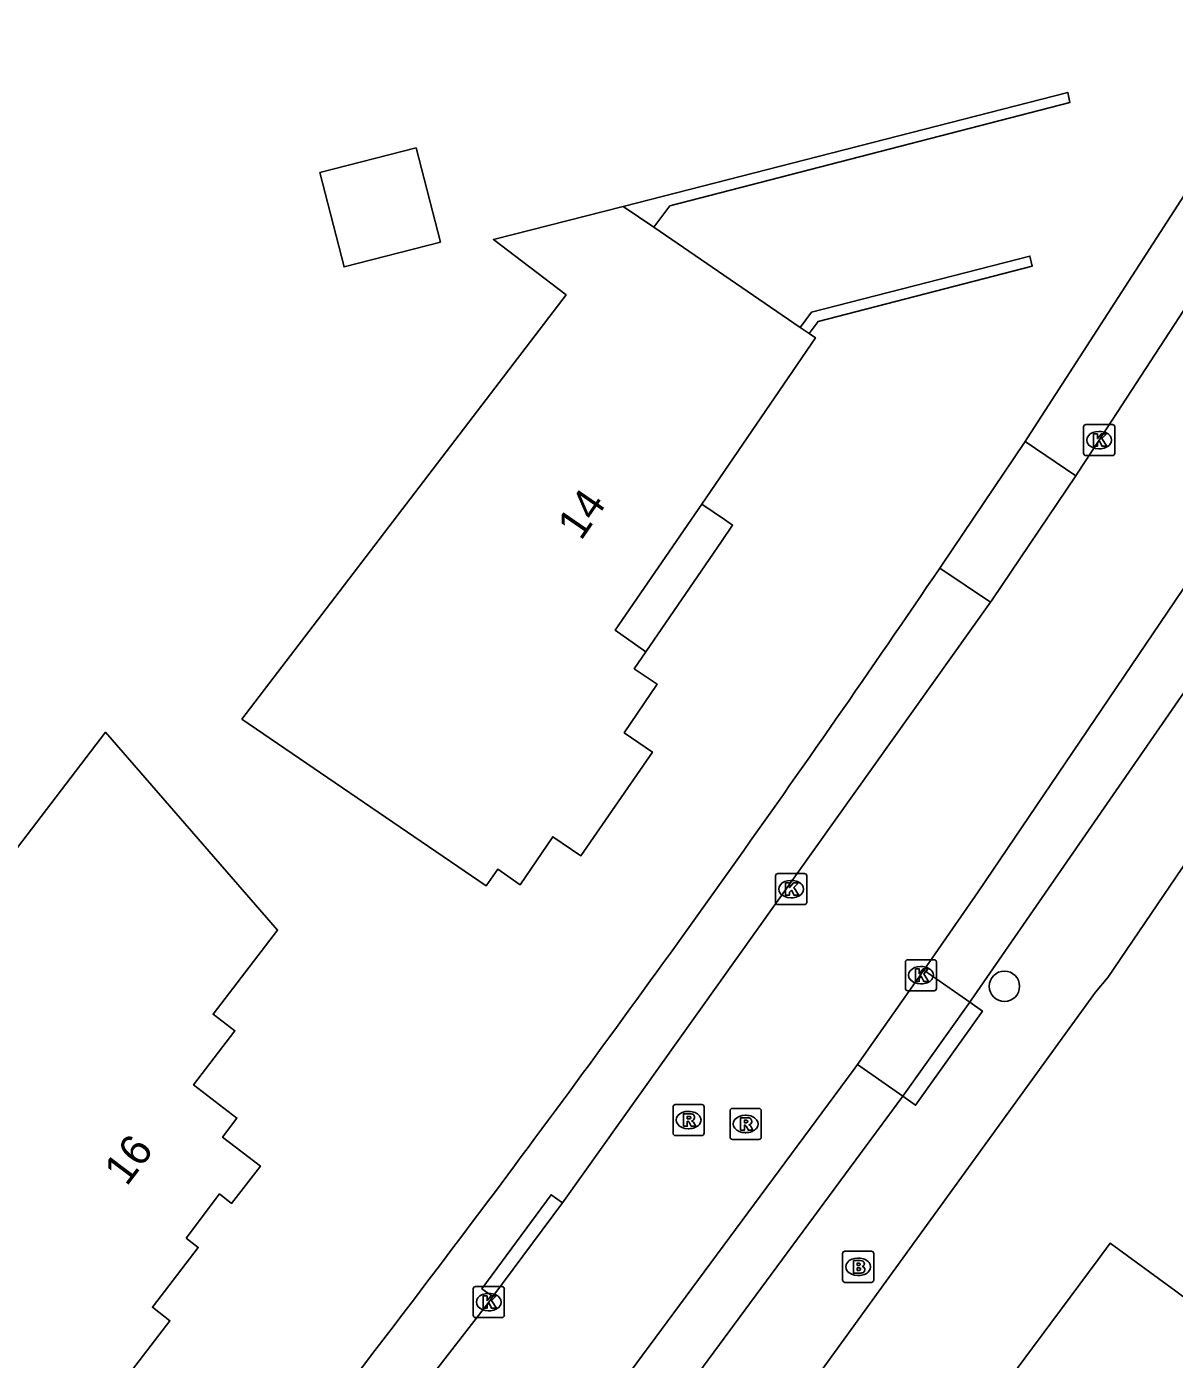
# Model space of a CAD drawing. Extents: x 158838 to 160074, y 386376 to 387776.
# Drawn here: x 159457.62 to 159494.56, y 386648.07 to 386690.99 of the extents above; entities that cross this region are included whole.
import ezdxf

# ---------------------------------------------------------------- set-up
doc = ezdxf.new("R2010")
doc.units = 0
for name, color, linetype in [('IMGEO_Boom', 7, 'Continuous'), ('IMGEO_Brandkraan', 7, 'Continuous'), ('IMGEO_Kolk', 7, 'Continuous'), ('IMGEO_Muur', 7, 'Continuous'), ('IMGEO_Pand', 7, 'Continuous'), ('IMGEO_Pand_nummerreeks', 7, 'Continuous'), ('IMGEO_Pand_overbouw', 7, 'Continuous'), ('IMGEO_Rijbaan_lokaal_gesloten', 7, 'Continuous'), ('IMGEO_Rioolput', 7, 'Continuous'), ('IMGEO_Voetpad_open', 7, 'Continuous')]:
    doc.layers.add(name, color=color, linetype=linetype)

msp = doc.modelspace()

# ---------------------------------------------------------------- linework, layer by layer
at = {"layer": 'IMGEO_Boom'}
msp.add_circle((159489.093, 386660.084), 0.489, dxfattribs=at)
at = {"layer": 'IMGEO_Brandkraan'}
for p, q in [((159483.884, 386650.623), (159483.884, 386651.475)), ((159483.959, 386651.549), (159484.811, 386651.549)), ((159484.372, 386651.329), (159484.397, 386651.329)), ((159484.885, 386651.475), (159484.885, 386650.623)), ((159484.811, 386650.549), (159483.959, 386650.549)), ((159484.395, 386650.769), (159484.37, 386650.769))]:
    msp.add_line(p, q, dxfattribs=at)
for points in [[(159483.884, 386650.623), (159483.884, 386651.475)], [(159483.959, 386651.549), (159484.811, 386651.549)], [(159484.885, 386651.475), (159484.885, 386650.623)], [(159484.232, 386651.249), (159484.232, 386650.849), (159484.445, 386650.849)], [(159484.463, 386651.249), (159484.232, 386651.249)], [(159484.411, 386651.168), (159484.357, 386651.168), (159484.357, 386651.092)], [(159484.357, 386651.092), (159484.41, 386651.092)], [(159484.419, 386651.016), (159484.357, 386651.016), (159484.357, 386650.935)], [(159484.357, 386650.935), (159484.419, 386650.935)], [(159484.811, 386650.549), (159483.959, 386650.549)]]:
    msp.add_lwpolyline(points, dxfattribs=at)
for centre, radius, start, end in [((159483.961, 386651.473), 0.0765, 91.552, 178.448), ((159483.961, 386651.473), 0.0765, 91.552, 178.448), ((159484.809, 386651.473), 0.0765, 1.552, 88.448), ((159484.809, 386651.473), 0.0765, 1.552, 88.448), ((159484.412, 386651.13), 0.0379, 267.8285, 90.9355), ((159484.42, 386650.975), 0.0404, 269.8759, 90.5077), ((159484.451, 386651.1), 0.251, 268.6676, 293.5347), ((159484.467, 386651.104), 0.145, 59.4692, 91.5367), ((159484.492, 386651.151), 0.0922, 285.5137, 58.1501), ((159484.497, 386650.959), 0.105, 301.3115, 78.989), ((159483.961, 386650.625), 0.0765, 181.552, 268.448), ((159483.961, 386650.625), 0.0765, 181.552, 268.448), ((159484.809, 386650.625), 0.0765, 271.552, 358.448), ((159484.809, 386650.625), 0.0765, 271.552, 358.448)]:
    msp.add_arc(centre, radius, start, end, dxfattribs=at)
for centre, major_axis, ratio, start_param, end_param in [((159484.371, 386651.049), (-0.387, 0.002), 0.722429, 4.712389, 7.853982), ((159484.396, 386651.049), (-0.39, 0.002), 0.717154, 1.570796, 4.712389)]:
    msp.add_ellipse(centre, major_axis=major_axis, ratio=ratio, start_param=start_param, end_param=end_param, dxfattribs=at)
at = {"layer": 'IMGEO_Kolk'}
for p, q in [((159491.642, 386677.253), (159491.642, 386678.105)), ((159491.717, 386678.179), (159492.569, 386678.179)), ((159492.13, 386677.959), (159492.155, 386677.959)), ((159492.643, 386678.105), (159492.643, 386677.253)), ((159492.569, 386677.179), (159491.717, 386677.179)), ((159492.153, 386677.399), (159492.128, 386677.399)), ((159481.802, 386663.715), (159482.654, 386663.715)), ((159481.727, 386662.789), (159481.727, 386663.641)), ((159482.215, 386663.495), (159482.24, 386663.495)), ((159482.728, 386663.641), (159482.728, 386662.789)), ((159482.238, 386662.935), (159482.213, 386662.935)), ((159482.654, 386662.715), (159481.802, 386662.715)), ((159485.905, 386660.016), (159485.905, 386660.868)), ((159485.98, 386660.942), (159486.832, 386660.942)), ((159486.393, 386660.722), (159486.418, 386660.722)), ((159486.906, 386660.868), (159486.906, 386660.016)), ((159486.832, 386659.942), (159485.98, 386659.942)), ((159486.416, 386660.162), (159486.391, 386660.162)), ((159472.068, 386650.413), (159472.92, 386650.413)), ((159471.993, 386649.487), (159471.993, 386650.339)), ((159472.481, 386650.193), (159472.506, 386650.193)), ((159472.994, 386650.339), (159472.994, 386649.487)), ((159472.504, 386649.633), (159472.479, 386649.633)), ((159472.92, 386649.413), (159472.068, 386649.413))]:
    msp.add_line(p, q, dxfattribs=at)
for points in [[(159491.642, 386677.253), (159491.642, 386678.105)], [(159491.717, 386678.179), (159492.569, 386678.179)], [(159491.963, 386677.879), (159492.086, 386677.879), (159492.086, 386677.728), (159492.216, 386677.879), (159492.38, 386677.879), (159492.234, 386677.728), (159492.387, 386677.479), (159492.235, 386677.479), (159492.15, 386677.643), (159492.086, 386677.576), (159492.086, 386677.479), (159491.963, 386677.479), (159491.963, 386677.879)], [(159492.643, 386678.105), (159492.643, 386677.253)], [(159492.569, 386677.179), (159491.717, 386677.179)], [(159481.802, 386663.715), (159482.654, 386663.715)], [(159481.727, 386662.789), (159481.727, 386663.641)], [(159482.048, 386663.415), (159482.171, 386663.415), (159482.171, 386663.264), (159482.301, 386663.415), (159482.465, 386663.415), (159482.319, 386663.264), (159482.472, 386663.015), (159482.32, 386663.015), (159482.235, 386663.179), (159482.171, 386663.112), (159482.171, 386663.015), (159482.048, 386663.015), (159482.048, 386663.415)], [(159482.728, 386663.641), (159482.728, 386662.789)], [(159482.654, 386662.715), (159481.802, 386662.715)], [(159485.905, 386660.016), (159485.905, 386660.868)], [(159485.98, 386660.942), (159486.832, 386660.942)], [(159486.906, 386660.868), (159486.906, 386660.016)], [(159486.226, 386660.642), (159486.349, 386660.642), (159486.349, 386660.491), (159486.479, 386660.642), (159486.643, 386660.642), (159486.497, 386660.491), (159486.65, 386660.242), (159486.498, 386660.242), (159486.413, 386660.406), (159486.349, 386660.339), (159486.349, 386660.242), (159486.226, 386660.242), (159486.226, 386660.642)], [(159486.832, 386659.942), (159485.98, 386659.942)], [(159472.068, 386650.413), (159472.92, 386650.413)], [(159471.993, 386649.487), (159471.993, 386650.339)], [(159472.314, 386650.113), (159472.437, 386650.113), (159472.437, 386649.962), (159472.567, 386650.113), (159472.731, 386650.113), (159472.585, 386649.962), (159472.738, 386649.713), (159472.586, 386649.713), (159472.501, 386649.877), (159472.437, 386649.81), (159472.437, 386649.713), (159472.314, 386649.713), (159472.314, 386650.113)], [(159472.994, 386650.339), (159472.994, 386649.487)], [(159472.92, 386649.413), (159472.068, 386649.413)]]:
    msp.add_lwpolyline(points, dxfattribs=at)
for centre, start, end in [((159491.719, 386678.103), 91.552, 178.448), ((159491.719, 386678.103), 91.552, 178.448), ((159492.567, 386678.103), 1.552, 88.448), ((159492.567, 386678.103), 1.552, 88.448), ((159491.719, 386677.255), 181.552, 268.448), ((159491.719, 386677.255), 181.552, 268.448), ((159492.567, 386677.255), 271.552, 358.448), ((159492.567, 386677.255), 271.552, 358.448), ((159481.804, 386663.639), 91.552, 178.448), ((159481.804, 386663.639), 91.552, 178.448), ((159482.652, 386663.639), 1.552, 88.448), ((159482.652, 386663.639), 1.552, 88.448), ((159481.804, 386662.791), 181.552, 268.448), ((159481.804, 386662.791), 181.552, 268.448), ((159482.652, 386662.791), 271.552, 358.448), ((159482.652, 386662.791), 271.552, 358.448), ((159485.982, 386660.866), 91.552, 178.448), ((159485.982, 386660.866), 91.552, 178.448), ((159486.83, 386660.866), 1.552, 88.448), ((159486.83, 386660.866), 1.552, 88.448), ((159485.982, 386660.018), 181.552, 268.448), ((159485.982, 386660.018), 181.552, 268.448), ((159486.83, 386660.018), 271.552, 358.448), ((159486.83, 386660.018), 271.552, 358.448), ((159472.07, 386650.337), 91.552, 178.448), ((159472.07, 386650.337), 91.552, 178.448), ((159472.918, 386650.337), 1.552, 88.448), ((159472.918, 386650.337), 1.552, 88.448), ((159472.07, 386649.489), 181.552, 268.448), ((159472.07, 386649.489), 181.552, 268.448), ((159472.918, 386649.489), 271.552, 358.448), ((159472.918, 386649.489), 271.552, 358.448)]:
    msp.add_arc(centre, 0.0765, start, end, dxfattribs=at)
for centre, major_axis, ratio, start_param, end_param in [((159492.129, 386677.679), (-0.387, 0.002), 0.722429, 4.712389, 7.853982), ((159492.154, 386677.679), (-0.39, 0.002), 0.717154, 1.570796, 4.712389), ((159482.214, 386663.215), (-0.387, 0.002), 0.722429, 4.712389, 7.853982), ((159482.239, 386663.215), (-0.39, 0.002), 0.717154, 1.570796, 4.712389), ((159486.392, 386660.442), (-0.387, 0.002), 0.722429, 4.712389, 7.853982), ((159486.417, 386660.442), (-0.39, 0.002), 0.717154, 1.570796, 4.712389), ((159472.48, 386649.913), (-0.387, 0.002), 0.722429, 4.712389, 7.853982), ((159472.505, 386649.913), (-0.39, 0.002), 0.717154, 1.570796, 4.712389)]:
    msp.add_ellipse(centre, major_axis=major_axis, ratio=ratio, start_param=start_param, end_param=end_param, dxfattribs=at)
at = {"layer": 'IMGEO_Muur'}
for points in [[(159476.823, 386685.207), (159491.131, 386688.877), (159491.202, 386688.552), (159478.326, 386685.224), (159477.803, 386684.535)], [(159482.519, 386681.3), (159482.879, 386681.794), (159489.914, 386683.607), (159489.99, 386683.281), (159483.094, 386681.494), (159482.805, 386681.113)]]:
    msp.add_lwpolyline(points, dxfattribs=at)
at = {"layer": 'IMGEO_Pand'}
for points in [[(159467.053, 386686.293), (159467.834, 386683.258), (159470.936, 386684.056), (159470.155, 386687.091), (159467.053, 386686.293)], [(159482.805, 386681.113), (159483.009, 386680.975), (159479.351, 386675.617), (159476.56, 386671.56), (159477.546, 386670.861), (159477.174, 386670.314), (159477.911, 386669.812), (159476.855, 386668.254), (159477.761, 386667.631), (159475.462, 386664.289), (159474.553, 386664.901), (159473.506, 386663.357), (159472.784, 386663.856), (159472.411, 386663.325), (159464.547, 386668.691), (159474.982, 386682.353), (159472.645, 386684.138), (159476.823, 386685.207)], [(159477.803, 386684.535), (159476.823, 386685.207)], [(159477.803, 386684.535), (159482.519, 386681.3)], [(159482.805, 386681.113), (159482.519, 386681.3)], [(159450.252, 386653.074), (159456.148, 386660.783), (159455.066, 386661.61), (159460.158, 386668.269), (159465.695, 386661.894), (159463.619, 386659.187), (159464.319, 386658.654), (159462.991, 386656.911), (159464.385, 386655.839), (159463.924, 386655.224), (159465.144, 386654.294), (159464.21, 386653.092), (159463.827, 386653.395), (159462.752, 386651.973), (159463.139, 386651.674), (159461.667, 386649.745), (159462.231, 386649.313), (159459.541, 386645.804), (159456.77, 386647.914), (159457.23, 386648.489), (159454.926, 386650.184), (159454.604, 386649.746), (159450.252, 386653.074)], [(159510.292, 386632.116), (159500.067, 386639.683), (159496.612, 386635.111), (159493.813, 386637.183), (159489.698, 386640.229), (159485.96, 386642.995), (159489.992, 386648.443), (159492.11, 386651.289), (159492.501, 386651.811), (159494.608, 386650.269), (159495.495, 386649.612), (159497.478, 386652.247), (159500, 386650.371), (159504.011, 386647.387), (159502.97, 386645.987), (159503.805, 386645.366), (159505.572, 386647.754), (159514.036, 386641.48), (159513.714, 386641.046), (159515.731, 386639.551)]]:
    msp.add_lwpolyline(points, dxfattribs=at)
at = {"layer": 'IMGEO_Pand_overbouw'}
msp.add_lwpolyline([(159477.546, 386670.861), (159479.98, 386674.411), (159480.341, 386674.941), (159480.078, 386675.12), (159479.351, 386675.617), (159476.56, 386671.56)], close=True, dxfattribs=at)
at = {"layer": 'IMGEO_Rijbaan_lokaal_gesloten'}
for points in [[(159491.393, 386676.531), (159491.469, 386676.644), (159492.103, 386677.614), (159497.335, 386685.65)], [(159491.393, 386676.531), (159488.703, 386672.537), (159488.647, 386672.459)], [(159486.494, 386660.609), (159488.253, 386663.123), (159495.988, 386674.563)], [(159488.647, 386672.459), (159474.87, 386653.114)], [(159484.364, 386657.566), (159486.494, 386660.609)], [(159476.255, 386646.598), (159484.227, 386657.37), (159484.364, 386657.566)], [(159474.87, 386653.114), (159472.629, 386650.095)], [(159472.629, 386650.095), (159472.496, 386649.912), (159463.597, 386638.445), (159463.101, 386637.845)]]:
    msp.add_lwpolyline(points, dxfattribs=at)
at = {"layer": 'IMGEO_Rioolput'}
for p, q in [((159478.424, 386655.351), (159478.424, 386656.203)), ((159478.499, 386656.277), (159479.351, 386656.277)), ((159478.912, 386656.057), (159478.937, 386656.057)), ((159479.425, 386656.203), (159479.425, 386655.351)), ((159480.262, 386655.224), (159480.262, 386656.076)), ((159480.337, 386656.15), (159481.189, 386656.15)), ((159481.263, 386656.076), (159481.263, 386655.224)), ((159480.75, 386655.93), (159480.775, 386655.93)), ((159479.351, 386655.277), (159478.499, 386655.277)), ((159478.935, 386655.497), (159478.91, 386655.497)), ((159481.189, 386655.15), (159480.337, 386655.15)), ((159480.773, 386655.37), (159480.748, 386655.37))]:
    msp.add_line(p, q, dxfattribs=at)
for points in [[(159478.424, 386655.351), (159478.424, 386656.203)], [(159478.499, 386656.277), (159479.351, 386656.277)], [(159479.425, 386656.203), (159479.425, 386655.351)], [(159480.262, 386655.224), (159480.262, 386656.076)], [(159480.337, 386656.15), (159481.189, 386656.15)], [(159481.263, 386656.076), (159481.263, 386655.224)], [(159479.013, 386655.975), (159478.761, 386655.977), (159478.761, 386655.577)], [(159478.761, 386655.577), (159478.885, 386655.577), (159478.885, 386655.739), (159478.896, 386655.739)], [(159478.939, 386655.896), (159478.885, 386655.896), (159478.885, 386655.815)], [(159478.885, 386655.815), (159478.937, 386655.815)], [(159478.943, 386655.71), (159479.014, 386655.577), (159479.154, 386655.577), (159479.089, 386655.703)], [(159480.851, 386655.848), (159480.599, 386655.85), (159480.599, 386655.45)], [(159480.599, 386655.45), (159480.723, 386655.45), (159480.723, 386655.612), (159480.734, 386655.612)], [(159480.777, 386655.769), (159480.723, 386655.769), (159480.723, 386655.688)], [(159480.723, 386655.688), (159480.775, 386655.688)], [(159480.781, 386655.583), (159480.852, 386655.45), (159480.992, 386655.45), (159480.927, 386655.576)], [(159479.351, 386655.277), (159478.499, 386655.277)], [(159481.189, 386655.15), (159480.337, 386655.15)]]:
    msp.add_lwpolyline(points, dxfattribs=at)
for centre, radius, start, end in [((159478.501, 386656.201), 0.0765, 91.552, 178.448), ((159478.501, 386656.201), 0.0765, 91.552, 178.448), ((159479.349, 386656.201), 0.0765, 1.552, 88.448), ((159479.349, 386656.201), 0.0765, 1.552, 88.448), ((159480.339, 386656.074), 0.0765, 91.552, 178.448), ((159480.339, 386656.074), 0.0765, 91.552, 178.448), ((159481.187, 386656.074), 0.0765, 1.552, 88.448), ((159481.187, 386656.074), 0.0765, 1.552, 88.448), ((159478.895, 386655.686), 0.0533, 26.0293, 88.6989), ((159478.921, 386656.004), 0.19, 274.7715, 282.9687), ((159478.945, 386655.8), 0.0964, 77.0061, 93.1865), ((159478.959, 386655.857), 0.0378, 276.6634, 79.6772), ((159479.012, 386655.865), 0.109, 350.3612, 89.416), ((159479.01, 386655.865), 0.112, 277.5842, 350.9817), ((159478.994, 386655.65), 0.108, 29.5134, 73.7905), ((159480.733, 386655.559), 0.0533, 26.0293, 88.6989), ((159480.759, 386655.877), 0.19, 274.7715, 282.9687), ((159480.783, 386655.673), 0.0964, 77.0061, 93.1865), ((159480.797, 386655.73), 0.0378, 276.6634, 79.6772), ((159480.85, 386655.738), 0.109, 350.3612, 89.416), ((159480.848, 386655.738), 0.112, 277.5842, 350.9817), ((159480.832, 386655.523), 0.108, 29.5134, 73.7905), ((159478.501, 386655.353), 0.0765, 181.552, 268.448), ((159478.501, 386655.353), 0.0765, 181.552, 268.448), ((159479.349, 386655.353), 0.0765, 271.552, 358.448), ((159479.349, 386655.353), 0.0765, 271.552, 358.448), ((159480.339, 386655.226), 0.0765, 181.552, 268.448), ((159480.339, 386655.226), 0.0765, 181.552, 268.448), ((159481.187, 386655.226), 0.0765, 271.552, 358.448), ((159481.187, 386655.226), 0.0765, 271.552, 358.448)]:
    msp.add_arc(centre, radius, start, end, dxfattribs=at)
for centre, major_axis, ratio, start_param, end_param in [((159478.911, 386655.777), (-0.387, 0.002), 0.722429, 4.712389, 7.853982), ((159478.936, 386655.777), (-0.39, 0.002), 0.717154, 1.570796, 4.712389), ((159480.749, 386655.65), (-0.387, 0.002), 0.722429, 4.712389, 7.853982), ((159480.774, 386655.65), (-0.39, 0.002), 0.717154, 1.570796, 4.712389)]:
    msp.add_ellipse(centre, major_axis=major_axis, ratio=ratio, start_param=start_param, end_param=end_param, dxfattribs=at)
at = {"layer": 'IMGEO_Voetpad_open'}
for points in [[(159524.846, 386728.532), (159523.607, 386726.844), (159523.829, 386721.437), (159523.936, 386720.207), (159523.989, 386717.606), (159523.81, 386715.012), (159523.4, 386712.444), (159522.762, 386709.923), (159521.901, 386707.468), (159520.825, 386705.101), (159506.854, 386682.053), (159500.252, 386671.907), (159500, 386671.529), (159492.426, 386660.371), (159492.025, 386659.896), (159480.297, 386643.692), (159466.865, 386626.712), (159452.919, 386610.024), (159444.818, 386600.823), (159442.679, 386598.473)], [(159511.714, 386722.925), (159511.746, 386722.739), (159511.952, 386719.617), (159511.887, 386716.039), (159511.811, 386715.214), (159511.639, 386714.228), (159511.379, 386713.262), (159511.034, 386712.323), (159510.606, 386711.419), (159500, 386693.513), (159499.829, 386693.238), (159489.836, 386677.746), (159489.757, 386677.629)], [(159487.016, 386673.557), (159487.077, 386673.647), (159489.757, 386677.629)], [(159489.757, 386677.629), (159491.393, 386676.531)], [(159488.647, 386672.459), (159487.016, 386673.557)], [(159497.546, 386673.509), (159494.875, 386669.563), (159488.022, 386659.633), (159487.977, 386659.57)], [(159487.977, 386659.57), (159486.494, 386660.609)], [(159487.977, 386659.57), (159488.386, 386659.284), (159486.234, 386656.254), (159485.827, 386656.543)], [(159487.977, 386659.57), (159485.827, 386656.543)], [(159484.364, 386657.566), (159485.827, 386656.543)], [(159485.827, 386656.543), (159477.708, 386645.554), (159477.681, 386645.519)], [(159472.629, 386650.095), (159472.275, 386650.344), (159474.5, 386653.37), (159474.87, 386653.114)]]:
    msp.add_lwpolyline(points, dxfattribs=at)
for centre, radius, start, end in [((159034.245, 386981.09), 547.337, 323.34107, 325.81472), ((158997.141, 387009.134), 593.846, 321.080124, 323.307898)]:
    msp.add_arc(centre, radius, start, end, dxfattribs=at)

# ---------------------------------------------------------------- texts
at = {"layer": 'IMGEO_Pand_nummerreeks'}
for s, rotation, p in [('14', 55.4741, (159475.462, 386674.411)), ('16', 52.9115, (159460.836, 386653.617))]:
    msp.add_text(s, height=1, rotation=rotation, dxfattribs=at).set_placement(p)

doc.saveas('drawing.dxf')
